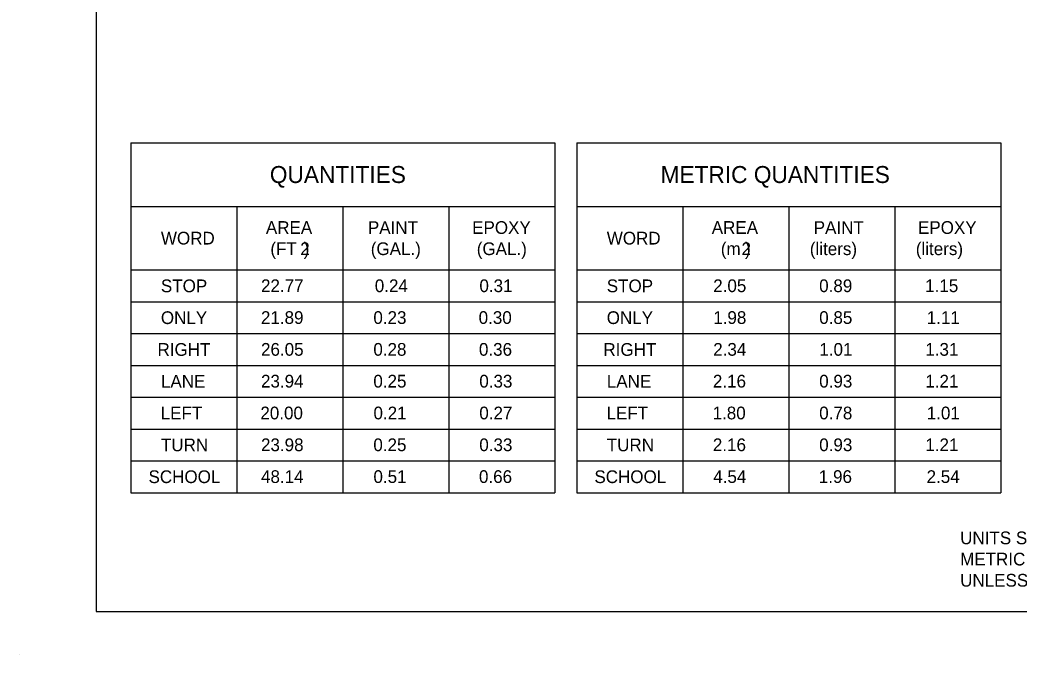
# Model space of a CAD drawing. Extents: x 49991.4 to 50021, y 49987.6 to 50011.4.
# Drawn here: x 49999.977 to 50004.689, y 49999.862 to 50002.852 of the extents above; entities that cross this region are included whole.
import ezdxf

# ---------------------------------------------------------------- set-up
doc = ezdxf.new("R2010")
doc.units = 0
doc.layers.add('Level 1', color=7, linetype='Continuous')
doc.layers.add('Level 2', color=7, linetype='Continuous')

msp = doc.modelspace()

# ---------------------------------------------------------------- linework, layer by layer
at = {"layer": 'Level 1'}
msp.add_line((49999.9766, 49999.8624), (49999.9766, 49999.8624), dxfattribs=at)
msp.add_lwpolyline([(50008.6146, 50011.2628), (50000.3356, 50011.2628), (50000.3356, 50000.0624), (50008.6146, 50000.0624)], close=True, dxfattribs=at)
at = {"layer": 'Level 2'}
for p, q in [((50000.4997, 50002.2732), (50000.4997, 50000.6232)), ((50000.4997, 50002.2732), (50002.4997, 50002.2732)), ((50002.4997, 50002.2732), (50002.4997, 50000.6232)), ((50002.6031, 50002.2732), (50002.6031, 50000.6232)), ((50002.6031, 50002.2732), (50004.6031, 50002.2732)), ((50004.6031, 50002.2732), (50004.6031, 50000.6232)), ((50000.4997, 50001.9732), (50002.4997, 50001.9732)), ((50000.9997, 50001.9732), (50000.9997, 50000.6232)), ((50001.4997, 50001.9732), (50001.4997, 50000.6232)), ((50001.9997, 50001.9732), (50001.9997, 50000.6232)), ((50002.6031, 50001.9732), (50004.6031, 50001.9732)), ((50003.1031, 50001.9732), (50003.1031, 50000.6232)), ((50003.6031, 50001.9732), (50003.6031, 50000.6232)), ((50004.1031, 50001.9732), (50004.1031, 50000.6232)), ((50000.4997, 50001.6732), (50002.4997, 50001.6732)), ((50002.6031, 50001.6732), (50004.6031, 50001.6732)), ((50000.4997, 50001.5232), (50002.4997, 50001.5232)), ((50002.6031, 50001.5232), (50004.6031, 50001.5232)), ((50000.4997, 50001.3732), (50002.4997, 50001.3732)), ((50002.6031, 50001.3732), (50004.6031, 50001.3732)), ((50000.4997, 50001.2232), (50002.4997, 50001.2232)), ((50002.6031, 50001.2232), (50004.6031, 50001.2232)), ((50000.4997, 50001.0732), (50002.4997, 50001.0732)), ((50002.6031, 50001.0732), (50004.6031, 50001.0732)), ((50000.4997, 50000.9232), (50002.4997, 50000.9232)), ((50002.6031, 50000.9232), (50004.6031, 50000.9232)), ((50000.4997, 50000.7732), (50002.4997, 50000.7732)), ((50002.6031, 50000.7732), (50004.6031, 50000.7732)), ((50000.4997, 50000.6232), (50002.4997, 50000.6232)), ((50002.6031, 50000.6232), (50004.6031, 50000.6232))]:
    msp.add_line(p, q, dxfattribs=at)

# ---------------------------------------------------------------- texts
for s, height, p in [('QUANTITIES', 0.08, (50001.1553, 50002.0834)), ('METRIC QUANTITIES', 0.08, (50002.9986, 50002.0834)), ('AREA', 0.06, (50001.1366, 50001.8435)), ('PAINT', 0.06, (50001.6178, 50001.8434)), ('EPOXY', 0.06, (50002.1096, 50001.8434)), ('AREA', 0.06, (50003.2399, 50001.8435)), ('PAINT', 0.06, (50003.7211, 50001.8434)), ('EPOXY', 0.06, (50004.2129, 50001.8434)), ('WORD', 0.06, (50000.6414, 50001.7934)), ('WORD', 0.06, (50002.7447, 50001.7934)), ('(FT', 0.06, (50001.1578, 50001.7435)), ('2', 0.06, (50001.2988, 50001.7435)), (')', 0.06, (50001.3149, 50001.7435)), ('(GAL.)', 0.06, (50001.6314, 50001.7434)), ('(GAL.)', 0.06, (50002.1314, 50001.7434)), ('(m', 0.06, (50003.2827, 50001.7435)), ('2', 0.06, (50003.3805, 50001.7435)), (')', 0.06, (50003.3967, 50001.7435)), ('(liters)', 0.06, (50003.7026, 50001.7434)), ('(liters)', 0.06, (50004.2026, 50001.7434)), ('STOP', 0.06, (50000.6414, 50001.5684)), ('22.77', 0.06, (50001.1136, 50001.5689)), ('0.24', 0.06, (50001.6504, 50001.5689)), ('0.31', 0.06, (50002.144, 50001.5689)), ('STOP', 0.06, (50002.7447, 50001.5684)), ('2.05', 0.06, (50003.2469, 50001.5689)), ('0.89', 0.06, (50003.7467, 50001.5689)), ('1.15', 0.06, (50004.2467, 50001.5689)), ('ONLY', 0.06, (50000.6412, 50001.4184)), ('21.89', 0.06, (50001.1133, 50001.4189)), ('0.23', 0.06, (50001.6437, 50001.4189)), ('0.30', 0.06, (50002.1403, 50001.4189)), ('ONLY', 0.06, (50002.7445, 50001.4184)), ('1.98', 0.06, (50003.2469, 50001.4189)), ('0.85', 0.06, (50003.7469, 50001.4189)), ('1.11', 0.06, (50004.2541, 50001.4189)), ('RIGHT', 0.06, (50000.6254, 50001.2684)), ('26.05', 0.06, (50001.1136, 50001.2689)), ('0.28', 0.06, (50001.6436, 50001.2689)), ('0.36', 0.06, (50002.1417, 50001.2689)), ('RIGHT', 0.06, (50002.7287, 50001.2684)), ('2.34', 0.06, (50003.2469, 50001.2689)), ('1.01', 0.06, (50003.7475, 50001.2689)), ('1.31', 0.06, (50004.2473, 50001.2689)), ('LANE', 0.06, (50000.6416, 50001.1184)), ('23.94', 0.06, (50001.1136, 50001.1189)), ('0.25', 0.06, (50001.6436, 50001.1189)), ('0.33', 0.06, (50002.1434, 50001.1189)), ('LANE', 0.06, (50002.7449, 50001.1184)), ('2.16', 0.06, (50003.2453, 50001.1189)), ('0.93', 0.06, (50003.7469, 50001.1189)), ('1.21', 0.06, (50004.2473, 50001.1189)), ('LEFT', 0.06, (50000.6404, 50000.9684)), ('20.00', 0.06, (50001.1106, 50000.9689)), ('0.21', 0.06, (50001.6442, 50000.9689)), ('0.27', 0.06, (50002.1434, 50000.9689)), ('LEFT', 0.06, (50002.7437, 50000.9684)), ('1.80', 0.06, (50003.2439, 50000.9689)), ('0.78', 0.06, (50003.7469, 50000.9689)), ('1.01', 0.06, (50004.2541, 50000.9689)), ('TURN', 0.06, (50000.6414, 50000.8184)), ('23.98', 0.06, (50001.1136, 50000.8189)), ('0.25', 0.06, (50001.6436, 50000.8189)), ('0.33', 0.06, (50002.1434, 50000.8189)), ('TURN', 0.06, (50002.7447, 50000.8184)), ('2.16', 0.06, (50003.2452, 50000.8189)), ('0.93', 0.06, (50003.7469, 50000.8189)), ('1.21', 0.06, (50004.2474, 50000.8189)), ('SCHOOL', 0.06, (50000.583, 50000.6684)), ('48.14', 0.06, (50001.1136, 50000.6689)), ('0.51', 0.06, (50001.6441, 50000.6689)), ('0.66', 0.06, (50002.1418, 50000.6689)), ('SCHOOL', 0.06, (50002.6863, 50000.6684)), ('4.54', 0.06, (50003.2469, 50000.6689)), ('1.96', 0.06, (50003.7452, 50000.6689)), ('2.54', 0.06, (50004.2534, 50000.6689)), ('UNITS SHOWN IN BRACKETS [] ARE ', 0.06, (50004.4117, 50000.38)), ('METRIC AND ARE IN MILLIMETERS (mm) ', 0.06, (50004.4117, 50000.28)), ('UNLESS OTHER UNITS ARE SHOWN.', 0.06, (50004.4117, 50000.18))]:
    msp.add_text(s, height=height, dxfattribs=at).set_placement(p)

doc.saveas('drawing.dxf')
